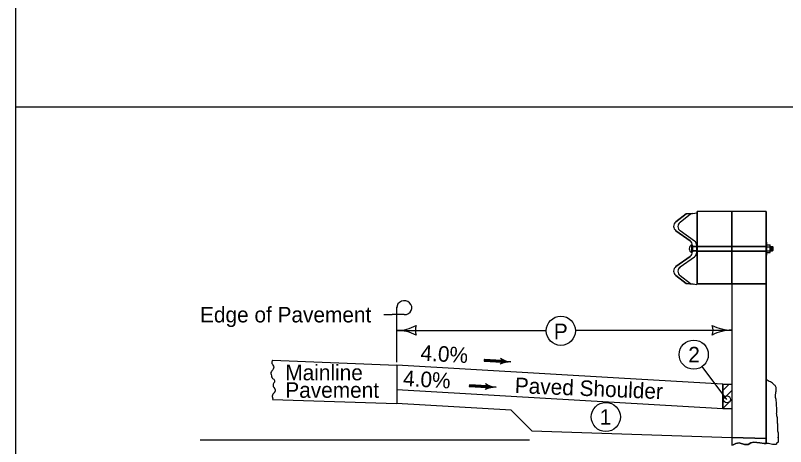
# Model space of a CAD drawing. Extents: x -1548 to 1548, y -960 to 993.
# Drawn here: x -1548 to -756, y -237 to 206 of the extents above; entities that cross this region are included whole.
import ezdxf

# ---------------------------------------------------------------- set-up
doc = ezdxf.new("R2010")
doc.units = 0
for name, color, linetype in [('dsnStdBorder', 7, 'Continuous'), ('dsnStdDimension', 7, 'Continuous'), ('dsnStdLabel', 7, 'Continuous'), ('dsnStdLineWork', 7, 'Continuous'), ('dsnStdNote', 7, 'Continuous'), ('dsnStdShading', 7, 'Continuous'), ('Level 4', 7, 'Continuous')]:
    doc.layers.add(name, color=color, linetype=linetype)

msp = doc.modelspace()

# ---------------------------------------------------------------- linework, layer by layer
at = {"layer": 'dsnStdBorder'}
msp.add_line((-1547.84, 650), (-1547.84, -960), dxfattribs=at)
at = {"layer": 'dsnStdDimension'}
for p, q in [((-1155.91, -117.69), (-1002.14, -117.69)), ((-972.16, -117.53), (-811.52, -117.53))]:
    msp.add_line(p, q, dxfattribs=at)
msp.add_circle((-987.15, -118.09), 15, dxfattribs=at)
for centre, radius, start, end in [((-1155.91, -75.19), 42.5, 270, 298.07249), ((-1155.91, -160.19), 42.5, 61.92751, 90), ((-1120.27, -117.69), 16.42, 162.26665, 197.73335), ((-847.15, -117.53), 16.42, 342.26665, 17.73335), ((-811.52, -75.03), 42.5, 241.92751, 270), ((-811.52, -160.03), 42.5, 90, 118.07249)]:
    msp.add_arc(centre, radius, start, end, dxfattribs=at)
at = {"layer": 'dsnStdLabel'}
for p, q in [((-1155.91, -114.37), (-1155.91, -93.51)), ((-1169.28, -101.52), (-1160.6, -101.52)), ((-1148.1, -101.52), (-1160.6, -101.52)), ((-1155.91, -150.3), (-1155.91, -114.37)), ((-1047.69, -149.53), (-1065.89, -148.48)), ((-1047.68, -148.53), (-1047.68, -148.53)), ((-1047.79, -150.47), (-1047.79, -150.47)), ((-1062.99, -175.62), (-1081.2, -174.57)), ((-1063.09, -176.56), (-1063.09, -176.56)), ((-1062.98, -174.61), (-1062.98, -174.61))]:
    msp.add_line(p, q, dxfattribs=at)
for points in [[(-1047.66, -148.59), (-1065.83, -147.54), (-1065.96, -149.42), (-1047.79, -150.47), (-1047.74, -148.86), (-1065.61, -147.76), (-1065.67, -149.26), (-1048.17, -150.21), (-1048.05, -149.09), (-1065.38, -148.03), (-1065.4, -149.03), (-1048.39, -150.01), (-1048.29, -149.3), (-1065.19, -148.25), (-1065.2, -148.81), (-1048.6, -149.75)], [(-1048.07, -147.34), (-1047.37, -148.5), (-1047.39, -150.15), (-1048.15, -151.55), (-1045.4, -150.68), (-1042.2, -150.03), (-1041.3, -149.9), (-1043.55, -149.35), (-1046.77, -148.12), (-1047.72, -147.59), (-1047.6, -151.1), (-1042.65, -149.88), (-1047.29, -148.3), (-1047.27, -150.72), (-1043.88, -149.79), (-1046.88, -148.93), (-1047.11, -150.31), (-1044.95, -149.81), (-1046.54, -149.3), (-1046.67, -149.96), (-1045.89, -149.8)], [(-1062.96, -174.68), (-1081.13, -173.63), (-1081.26, -175.51), (-1063.09, -176.56), (-1063.04, -174.94), (-1080.91, -173.85), (-1080.97, -175.35), (-1063.47, -176.3), (-1063.35, -175.18), (-1080.68, -174.11), (-1080.7, -175.11), (-1063.69, -176.1), (-1063.6, -175.39), (-1080.49, -174.33), (-1080.5, -174.9), (-1063.9, -175.83)], [(-1063.37, -173.42), (-1062.67, -174.59), (-1062.69, -176.24), (-1063.45, -177.63), (-1060.7, -176.77), (-1057.5, -176.12), (-1056.6, -175.98), (-1058.85, -175.44), (-1062.07, -174.21), (-1063.02, -173.67), (-1062.9, -177.18), (-1057.95, -175.97), (-1062.59, -174.39), (-1062.57, -176.81), (-1059.18, -175.88), (-1062.18, -175.01), (-1062.41, -176.4), (-1060.25, -175.9), (-1061.84, -175.39), (-1061.97, -176.05), (-1061.19, -175.88)]]:
    msp.add_lwpolyline(points, dxfattribs=at)
for centre, major_axis, start_param, end_param in [((-1148.1, -94.38), (-7.81, 0), 1.570796, 6.283185), ((-1051.46, -149.32), (3.88, 0), 5.202895, 7.237436), ((-1039.19, -170.31), (22.17, 0), 1.537172, 2.061295), ((-1036.4, -129.89), (-22.17, 0), 0.954258, 1.478381), ((-1066.76, -175.4), (3.88, 0), 5.202895, 7.237436), ((-1051.7, -155.98), (-22.17, 0), 0.954258, 1.478381), ((-1054.49, -196.4), (22.17, 0), 1.537172, 2.061295)]:
    msp.add_ellipse(centre, major_axis=major_axis, ratio=0.913811, start_param=start_param, end_param=end_param, dxfattribs=at)
at = {"layer": 'dsnStdLineWork'}
for p, q in [((-869.01, -6.08), (-858.24, 2.32)), ((-864.58, -6.31), (-853.8, 2.1)), ((-858.24, 2.32), (-851.91, 2.43)), ((-853.8, 2.1), (-847.46, 3.22)), ((-775.97, 4.68), (-847.07, 4.68)), ((-847.07, -69.97), (-847.07, 4.68)), ((-811.52, -69.97), (-811.52, 4.68)), ((-775.97, 4.68), (-775.97, -233.96)), ((-854.3, -25.61), (-868.81, -15.2)), ((-849.83, -25.85), (-864.39, -15.4)), ((-852.68, -37.72), (-852.68, -29.64)), ((-852.68, -31.33), (-847.25, -31.33)), ((-851.91, -37.06), (-851.91, -30.25)), ((-851.73, -31.33), (-847.07, -31.33)), ((-847.46, -33.87), (-847.46, -30.47)), ((-847.06, -30.99), (-775.97, -30.99)), ((-847.06, -31.33), (-775.97, -31.33)), ((-775.97, -27.02), (-775.29, -27.02)), ((-775.29, -40.35), (-775.29, -27.02)), ((-775.29, -29.65), (-772.33, -29.65)), ((-771.96, -36.72), (-771.96, -30.66)), ((-771.96, -31.36), (-769.59, -31.36)), ((-771.07, -31.36), (-771.07, -36.02)), ((-770.33, -31.36), (-770.33, -36.02)), ((-769.59, -31.36), (-769.14, -31.89)), ((-769.59, -31.36), (-769.59, -36.02)), ((-852.68, -35.99), (-847.07, -35.99)), ((-851.91, -37.06), (-851.91, -33.65)), ((-851.91, -33.65), (-851.91, -37.06)), ((-847.46, -37.28), (-847.46, -33.87)), ((-847.46, -33.87), (-847.46, -37.28)), ((-847.07, -36.33), (-775.97, -36.33)), ((-847.06, -35.99), (-775.97, -35.99)), ((-775.29, -31.67), (-772.33, -31.67)), ((-775.29, -35.71), (-772.33, -35.71)), ((-775.29, -37.73), (-772.33, -37.73)), ((-771.96, -36.02), (-769.59, -36.02)), ((-769.14, -35.49), (-769.59, -36.02)), ((-769.14, -31.89), (-769.14, -35.49)), ((-868.81, -52.11), (-854.3, -41.69)), ((-864.39, -52.34), (-849.83, -41.89)), ((-775.97, -40.35), (-775.29, -40.35)), ((-858.24, -69.62), (-869.01, -61.23)), ((-853.8, -69.84), (-864.58, -61.43)), ((-851.14, -70.31), (-858.24, -69.62)), ((-847.46, -70.96), (-853.8, -69.84)), ((-811.52, -69.97), (-847.07, -69.97)), ((-811.52, -69.97), (-811.52, -235.78)), ((-1283.66, -148.26), (-1155.91, -153.44)), ((-1155.91, -153.44), (-1155.91, -178.63)), ((-820.76, -179.68), (-814.01, -172.93)), ((-820.76, -172.93), (-820.76, -197.96)), ((-820.76, -172.93), (-811.52, -172.93)), ((-1155.91, -178.63), (-1155.91, -193.04)), ((-820.76, -188.86), (-811.52, -179.63)), ((-765.92, -179.7), (-765.92, -179.7)), ((-1283.4, -188.83), (-1156.12, -193.03)), ((-820.62, -197.95), (-811.52, -188.86)), ((-1038.25, -199.83), (-1156.08, -193.03)), ((-1038.25, -199.83), (-1016.91, -221.04)), ((-820.76, -197.96), (-811.52, -197.96)), ((-1016.91, -221.04), (-811.52, -227.75)), ((-1357.97, -230.29), (-1019.46, -230.29))]:
    msp.add_line(p, q, dxfattribs=at)
for points in [[(-772.26, -31.67), (-772.19, -31.62), (-772.12, -31.52), (-772.03, -31.3), (-771.98, -31.01), (-771.97, -32.96), (-772.03, -32.45), (-772.08, -32.08), (-772.2, -31.75), (-772.26, -31.67), (-772.21, -31.66), (-772.1, -31.51), (-772.01, -31.29), (-771.99, -31.13), (-771.99, -32.67), (-772.06, -32.18), (-772.12, -31.91), (-772.22, -31.69), (-772.19, -31.68), (-772.05, -31.46), (-772.01, -31.31), (-772.01, -32.41), (-772.2, -31.7), (-772.03, -31.42), (-772.03, -32.28), (-772.18, -31.71), (-772.05, -31.49), (-772.05, -32.13), (-772.16, -31.73), (-772.07, -31.56), (-772.07, -31.97), (-772.14, -31.74), (-772.08, -31.63), (-772.08, -31.83), (-772.11, -31.76), (-772.1, -31.71)], [(-771.97, -36.39), (-772.02, -36.13), (-772.07, -35.95), (-772.15, -35.8), (-772.27, -35.71), (-772.19, -35.61), (-772.11, -35.39), (-772.05, -35.08), (-771.97, -34.33), (-771.97, -36.4), (-771.99, -36.26), (-772.04, -36.04), (-772.11, -35.83), (-772.23, -35.72), (-772.19, -35.63), (-772.13, -35.48), (-772.03, -34.98), (-771.99, -34.6), (-771.99, -36.21), (-772.02, -36.09), (-772.07, -35.92), (-772.19, -35.72), (-772.14, -35.55), (-772.06, -35.22), (-772.01, -34.89), (-772.01, -36.05), (-772.05, -35.92), (-772.16, -35.73), (-772.12, -35.51), (-772.07, -35.26), (-772.03, -35.08), (-772.03, -35.95), (-772.09, -35.84), (-772.14, -35.73), (-772.05, -35.27), (-772.05, -35.87), (-772.12, -35.73), (-772.07, -35.44), (-772.07, -35.79), (-772.11, -35.72), (-772.09, -35.62), (-772.09, -35.7)], [(-765.45, -203.54), (-765.51, -203.81), (-765.51, -204.01), (-765.51, -204.21), (-765.51, -204.4), (-765.51, -204.6), (-765.51, -204.79), (-765.51, -205.08), (-765.51, -205.28), (-765.41, -205.57), (-765.32, -205.87), (-765.12, -206.06), (-765.12, -206.26), (-765.02, -206.45), (-765.02, -206.65), (-765.02, -206.84), (-764.92, -206.94), (-764.92, -207.14), (-764.92, -207.33), (-764.92, -207.53), (-764.92, -207.72), (-764.92, -207.92), (-764.92, -208.21), (-764.92, -208.5), (-764.92, -208.7), (-764.92, -208.99), (-764.92, -209.19), (-764.92, -209.38), (-764.83, -209.48), (-764.83, -209.68), (-764.83, -209.87), (-764.83, -210.07), (-764.83, -210.26), (-764.83, -210.46), (-764.83, -210.65), (-764.83, -210.85), (-764.83, -211.04), (-764.83, -211.24), (-764.83, -211.44), (-764.83, -211.63), (-764.83, -211.83), (-764.83, -212.02), (-764.83, -212.22), (-764.83, -212.41), (-764.83, -212.61), (-764.83, -212.8), (-764.83, -213), (-764.73, -213.1), (-764.73, -213.29), (-764.73, -213.49), (-764.63, -213.58), (-764.63, -213.78), (-764.63, -213.98), (-764.53, -214.07), (-764.53, -214.27), (-764.53, -214.46), (-764.53, -214.66), (-764.53, -214.95), (-764.44, -215.25), (-764.44, -215.44), (-764.44, -215.64), (-764.44, -215.83), (-764.44, -216.03), (-764.44, -216.22), (-764.44, -216.42), (-764.44, -216.61), (-764.44, -216.81), (-764.44, -217), (-764.44, -217.2), (-764.44, -217.4), (-764.44, -217.59), (-764.44, -217.79), (-764.44, -217.98), (-764.44, -218.18), (-764.44, -218.37), (-764.44, -218.57), (-764.44, -218.76), (-764.44, -218.96), (-764.44, -219.15), (-764.44, -219.35), (-764.44, -219.54), (-764.44, -219.74), (-764.44, -219.94), (-764.44, -220.13), (-764.44, -220.33), (-764.44, -220.52), (-764.44, -220.72), (-764.44, -220.91), (-764.34, -221.01), (-764.34, -221.3), (-764.34, -221.5), (-764.24, -221.69), (-764.14, -221.99), (-764.14, -222.18), (-764.04, -222.28), (-764.04, -222.48), (-763.95, -222.57), (-763.85, -222.67), (-763.85, -222.87), (-763.85, -223.06), (-763.85, -223.26), (-763.75, -223.36), (-763.75, -223.55), (-763.75, -223.75), (-763.75, -223.94), (-763.75, -224.14), (-763.75, -224.33), (-763.75, -224.53), (-763.75, -224.72), (-763.75, -224.92), (-763.75, -225.11), (-763.75, -225.31), (-763.75, -225.5), (-763.75, -225.7), (-763.75, -225.9), (-763.75, -226.09), (-763.75, -226.29), (-763.75, -226.48), (-763.75, -226.68), (-763.75, -226.87), (-763.75, -227.07), (-763.75, -227.26), (-763.75, -227.46), (-763.75, -227.65), (-763.75, -227.85), (-763.75, -228.04), (-763.75, -228.24), (-763.75, -228.24), (-763.75, -227.95), (-763.75, -227.75), (-763.75, -227.56), (-763.75, -227.75), (-763.75, -227.95), (-763.75, -228.14), (-763.75, -228.34), (-763.75, -228.53), (-763.75, -228.73), (-763.75, -228.92), (-763.75, -229.12), (-763.75, -229.32), (-763.75, -229.51), (-763.75, -229.71), (-763.75, -229.9), (-763.75, -230.1), (-763.75, -230.29), (-763.75, -230.49), (-763.85, -230.59), (-763.85, -230.78), (-763.85, -230.98), (-763.85, -231.17), (-763.85, -231.37), (-763.85, -231.56), (-763.85, -231.76), (-763.85, -231.95), (-763.85, -232.15), (-763.85, -232.34), (-763.85, -232.54), (-763.95, -232.64), (-764.04, -232.83), (-764.14, -232.93), (-764.24, -233.03), (-764.34, -233.13), (-764.53, -233.22), (-764.73, -233.22), (-764.83, -233.32), (-764.92, -233.42), (-765.02, -233.52), (-765.22, -233.61), (-765.32, -233.71), (-765.32, -233.91), (-765.41, -234), (-765.41, -234.2), (-765.41, -234.4), (-765.41, -234.59), (-765.41, -234.79), (-765.41, -234.88), (-765.41, -234.69)], [(-765.45, -235.01), (-769.6, -235.13), (-773.74, -233.96), (-778.3, -233.96), (-782.54, -233.54), (-788.79, -232.79), (-791.86, -233.43), (-794.51, -235.23), (-798.22, -235.02), (-803.84, -233.43), (-807.12, -233.96), (-809.88, -235.55), (-811.52, -235.78)]]:
    msp.add_lwpolyline(points, dxfattribs=at)
for centre, radius, start, end in [((-865.53, -10.57), 5.68, 127.75002, 234.69086), ((-861.08, -10.79), 5.68, 127.75002, 234.69086), ((-850.61, -33.67), 4.54, 117.20289, 242.8461), ((-857.58, -30.25), 5.68, 360, 54.69099), ((-853.14, -30.47), 5.68, 360, 54.69099), ((-857.58, -37.06), 5.68, 305.30901, 0), ((-853.14, -37.28), 5.68, 305.30901, 0), ((-865.53, -56.74), 5.68, 125.30914, 232.24998), ((-861.08, -56.96), 5.68, 125.30914, 232.24998)]:
    msp.add_arc(centre, radius, start, end, dxfattribs=at)
for centre in [(-772.33, -30.66), (-772.33, -36.72)]:
    msp.add_ellipse(centre, major_axis=(0, -1.01), ratio=0.362258, start_param=6.283156, end_param=9.424748, dxfattribs=at)
for points in [[(-1283.66, -148.26), (-1284.16, -151.86), (-1283.12, -153.37), (-1282.25, -155.67), (-1282.86, -157.73), (-1284.76, -160.1), (-1285.28, -162), (-1284.76, -164.3), (-1283.9, -166.67), (-1282.86, -167.39), (-1281.47, -169.92), (-1281.48, -170.76)], [(-1281.48, -170.76), (-1281.69, -171), (-1281.89, -171.27), (-1282.24, -171.82), (-1282.74, -173.04), (-1282.92, -174.28), (-1282.88, -174.86), (-1282.82, -175.14), (-1282.78, -175.28), (-1282.73, -175.41), (-1282.52, -175.79), (-1282.24, -176.15), (-1281.94, -176.51), (-1281.69, -176.91), (-1281.55, -177.2), (-1281.41, -177.48), (-1281.15, -178.05), (-1280.82, -179.21), (-1280.82, -179.34), (-1280.81, -179.46), (-1280.96, -180.24), (-1281.17, -180.76), (-1281.43, -181.27), (-1281.88, -181.91), (-1282.39, -182.45), (-1282.91, -183), (-1283.14, -183.3), (-1283.34, -183.64), (-1283.55, -184.12), (-1283.7, -184.59), (-1283.8, -185.07), (-1283.84, -185.31), (-1283.85, -185.43), (-1283.86, -185.54), (-1283.81, -186.05), (-1283.66, -186.57), (-1283.48, -187.08), (-1283.4, -188.83)], [(-765.45, -203.54), (-765.13, -200.64), (-765.35, -195.77), (-765.79, -190.02), (-766.46, -185.6), (-766.24, -182.28), (-765.79, -178.08), (-766.46, -174.99), (-768.67, -173), (-770.66, -171.23), (-772.87, -170.12), (-775.08, -168.79), (-775.97, -168.13)]]:
    msp.add_spline(points, degree=3, dxfattribs=at)
at = {"layer": 'dsnStdNote'}
for centre, radius in [((-850.56, -142.64), 15), ((-816.44, -188.76), 3.58), ((-940.96, -206.8), 15)]:
    msp.add_circle(centre, radius, dxfattribs=at)
at = {"layer": 'dsnStdShading'}
for p, q in [((-858.24, 2.32), (-869.01, -6.08)), ((-851.91, 2.43), (-858.24, 2.32)), ((-853.8, 2.1), (-851.91, 2.43)), ((-868.81, -15.2), (-854.3, -25.61)), ((-851.91, -30.25), (-851.91, -31.33)), ((-851.91, -31.33), (-847.46, -31.33)), ((-851.91, -31.33), (-851.91, -33.65)), ((-851.73, -31.33), (-851.91, -31.33)), ((-847.46, -31.33), (-851.73, -31.33)), ((-847.46, -31.33), (-847.46, -30.47)), ((-851.91, -33.65), (-851.91, -35.99)), ((-847.46, -35.99), (-851.91, -35.99)), ((-851.91, -35.99), (-851.91, -37.06)), ((-851.91, -35.99), (-847.46, -35.99)), ((-851.91, -37.06), (-851.91, -37.06)), ((-847.46, -37.28), (-847.46, -35.99)), ((-854.3, -41.69), (-868.81, -52.11)), ((-869.01, -61.23), (-858.24, -69.62)), ((-853.8, -69.84), (-864.56, -61.44)), ((-858.24, -69.62), (-851.14, -70.31)), ((-851.14, -70.31), (-853.8, -69.84))]:
    msp.add_line(p, q, dxfattribs=at)
for points in [[(-864.58, -6.31), (-864.56, -6.3), (-853.8, 2.1)], [(-811.52, -30.99), (-811.52, 4.68), (-847.07, 4.68), (-847.07, -30.99), (-847.06, -30.99), (-811.52, -30.99)], [(-775.97, -30.99), (-775.97, -27), (-775.97, 4.68), (-811.52, 4.68), (-811.52, -30.99), (-775.97, -30.99)], [(-864.58, -6.31), (-864.58, -6.31)], [(-849.86, -25.83), (-849.83, -25.85), (-864.37, -15.42)], [(-864.37, -15.42), (-864.37, -15.42)], [(-847.46, -35.99), (-847.46, -33.87), (-847.46, -31.33)], [(-847.07, -31.33), (-847.07, -35.99), (-847.06, -35.99), (-811.52, -35.99), (-811.52, -31.33), (-847.06, -31.33), (-847.07, -31.33)], [(-775.97, -35.99), (-775.97, -31.33), (-811.52, -31.33), (-811.52, -35.99), (-775.97, -35.99)], [(-851.91, -33.65), (-851.91, -33.65)], [(-851.91, -37.06), (-851.91, -37.06)], [(-847.07, -36.33), (-847.07, -69.97), (-811.52, -69.97), (-811.52, -36.33), (-847.07, -36.33)], [(-775.97, -69.97), (-775.97, -40.33), (-775.97, -36.33), (-811.52, -36.33), (-811.52, -69.97), (-775.97, -69.97)], [(-864.39, -52.34), (-864.37, -52.32), (-849.86, -41.91), (-849.83, -41.89)], [(-849.83, -41.89), (-849.83, -41.89)], [(-864.39, -52.34), (-864.39, -52.34)], [(-864.56, -61.44), (-864.56, -61.45)], [(-775.97, -228.91), (-775.97, -69.97), (-811.52, -69.97), (-811.52, -172.93), (-811.52, -179.63), (-811.52, -179.63), (-811.52, -179.63), (-811.52, -188.86), (-811.52, -188.86), (-811.52, -188.86), (-811.52, -198), (-811.52, -198), (-811.52, -198), (-811.52, -204.93), (-811.52, -227.75), (-775.97, -228.91)], [(-820.76, -197.96), (-820.76, -188.86), (-820.76, -179.68), (-820.76, -172.93), (-927.46, -166.73), (-1155.91, -153.44), (-1155.91, -178.63), (-820.76, -197.96)], [(-775.97, -228.91), (-811.52, -227.75), (-811.52, -235.78), (-809.88, -235.55), (-807.12, -233.96), (-803.84, -233.43), (-798.22, -235.02), (-794.51, -235.23), (-791.86, -233.43), (-788.79, -232.79), (-782.54, -233.54), (-778.3, -233.96), (-775.97, -233.96), (-775.97, -228.91)]]:
    msp.add_lwpolyline(points, dxfattribs=at)
for centre, start, end in [((-865.53, -10.57), 127.75002, 234.69086), ((-861.08, -10.79), 127.94699, 234.69086), ((-857.58, -30.25), 360, 54.69099), ((-853.14, -30.47), 360, 54.69099), ((-857.58, -37.06), 305.30901, 0), ((-853.14, -37.28), 305.67034, 360), ((-865.53, -56.74), 125.30914, 232.24998), ((-861.08, -56.96), 125.66008, 232.24998)]:
    msp.add_arc(centre, 5.68, start, end, dxfattribs=at)
at = {"layer": 'Level 4'}
for p, q in [((607.73, 112), (-1547.84, 112)), ((-816.44, -188.76), (-841.82, -154.84))]:
    msp.add_line(p, q, dxfattribs=at)

# ---------------------------------------------------------------- texts
at = {"layer": 'dsnStdDimension'}
msp.add_text('P', height=16, dxfattribs=at).set_placement((-994.38, -126.77))
at = {"layer": 'dsnStdLabel'}
for s, p in [('Edge of Pavement', (-1358.04, -109.52)), ('Mainline', (-1270.38, -169.07)), ('Pavement', (-1270.38, -187.07))]:
    msp.add_text(s, height=16, dxfattribs=at).set_placement(p)
for s, rotation, p in [('4.0%', 356.69917, (-1131.72, -148.59)), ('4.0%', 356.69917, (-1149.67, -174.77)), ('Paved Shoulder ', 357.5923, (-1034.72, -182.11))]:
    msp.add_text(s, height=16, rotation=rotation, dxfattribs=at).set_placement(p)
at = {"layer": 'dsnStdNote'}
for s, p in [('2', (-856.18, -150.64)), ('1', (-947.19, -214.8))]:
    msp.add_text(s, height=16, dxfattribs=at).set_placement(p)

doc.saveas('drawing.dxf')
